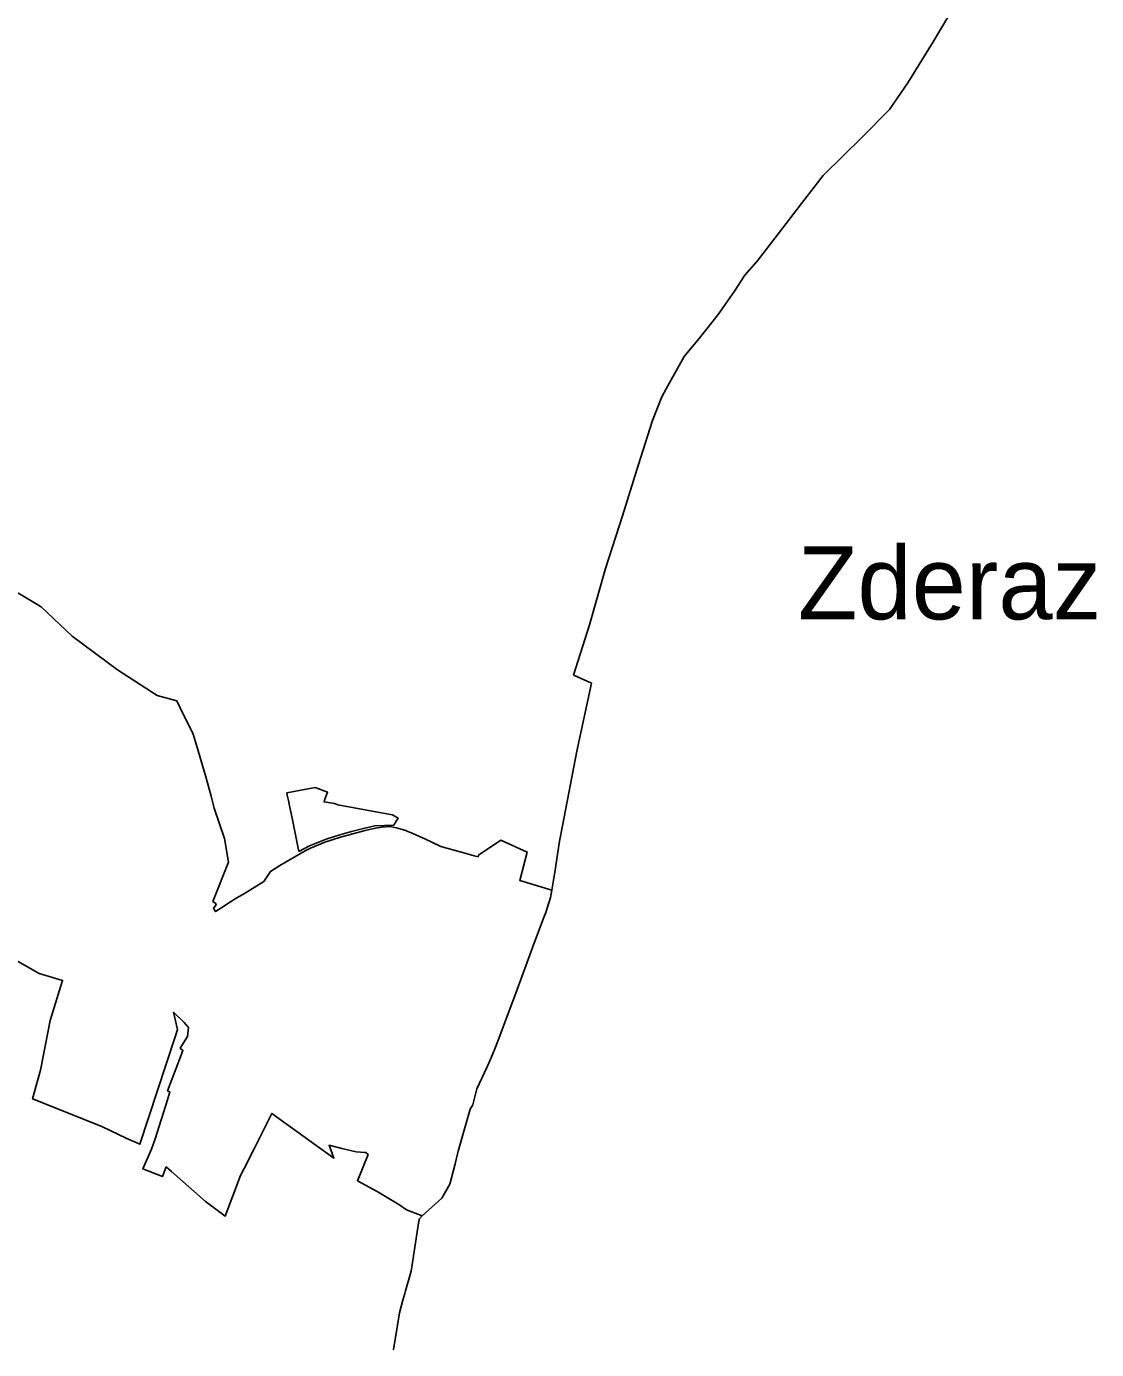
# Model space of a CAD drawing. Extents: x -630160 to -627062, y -1088658 to -1084740.
# Drawn here: x -628278 to -627397, y -1087158 to -1086070 of the extents above; entities that cross this region are included whole.
import ezdxf

# ---------------------------------------------------------------- set-up
doc = ezdxf.new("R2010")
doc.units = 0
for name, color, linetype in [('HRA_KU', 7, 'Continuous'), ('KU_OST', 7, 'Continuous'), ('OVNE_PRE', 7, 'Continuous'), ('OVNE_SET', 7, 'Continuous'), ('OVNI_SET', 7, 'Continuous')]:
    doc.layers.add(name, color=color, linetype=linetype)

msp = doc.modelspace()

# ---------------------------------------------------------------- linework, layer by layer
at = {"layer": 'HRA_KU'}
msp.add_lwpolyline([(-627518.5, -1086060.5), (-627531.4, -1086082.2), (-627552.3, -1086116), (-627567.3, -1086138), (-627589.2, -1086160.1), (-627621.8, -1086192.2), (-627639.7, -1086215.4), (-627658.8, -1086240.1), (-627676.3, -1086262.7), (-627686.3, -1086274.3), (-627695, -1086287.5), (-627708.2, -1086306.6), (-627722.8, -1086325.1), (-627736.2, -1086341.3), (-627751, -1086367.9), (-627754.6, -1086374.4), (-627762.4, -1086394), (-627774.2, -1086430.8), (-627787, -1086472.4), (-627801, -1086515.6), (-627814.2, -1086562.1), (-627827.3, -1086603.4), (-627824.1, -1086604.8), (-627812.7, -1086609.9), (-627824.6, -1086666.1), (-627836.4, -1086727.4), (-627838.8, -1086740.1), (-627842.8, -1086765.5), (-627845.3, -1086780.4), (-627846.4, -1086786.3), (-627850.2, -1086798.7), (-627852, -1086803.5), (-627861.3, -1086828.5), (-627873.8, -1086862.1), (-627890.6, -1086906.9), (-627891, -1086908.3), (-627894.5, -1086917), (-627898.5, -1086925.8), (-627906.9, -1086943.9), (-627910.3, -1086956.9), (-627912.4, -1086960.5), (-627912.4, -1086960.7), (-627922.2, -1086995.2), (-627922.8, -1086997.4), (-627924.9, -1087005.5), (-627929.2, -1087022.2), (-627935.8, -1087033.8), (-627951.8, -1087048.3), (-627954.1, -1087050.7), (-627954.4, -1087051), (-627954.5, -1087051.6), (-627954.9, -1087054.3), (-627961.1, -1087094), (-627965.6, -1087110.2), (-627966.2, -1087112.4), (-627967.7, -1087117.7), (-627970.6, -1087128.1), (-627972.3, -1087138.4), (-627975.1, -1087155), (-627975.6, -1087158), (-627975.7, -1087158.7)], dxfattribs=at)
at = {"layer": 'OVNE_PRE'}
for points in [[(-627518.5, -1086060.5), (-627531.4, -1086082.2), (-627552.3, -1086116), (-627567.3, -1086138), (-627589.2, -1086160.1), (-627621.8, -1086192.2), (-627639.7, -1086215.4), (-627658.8, -1086240.1), (-627676.3, -1086262.7), (-627686.3, -1086274.3), (-627695, -1086287.5), (-627708.2, -1086306.6), (-627722.8, -1086325.1), (-627736.2, -1086341.3), (-627751, -1086367.9), (-627754.6, -1086374.4), (-627762.4, -1086394), (-627774.2, -1086430.8), (-627787, -1086472.4), (-627801, -1086515.6), (-627814.2, -1086562.1), (-627827.3, -1086603.4), (-627824.1, -1086604.8), (-627812.7, -1086609.9), (-627824.6, -1086666.1), (-627836.4, -1086727.4), (-627838.8, -1086740.1), (-627842.8, -1086765.5), (-627845.3, -1086780.4)], [(-627951.8, -1087048.3), (-627954.1, -1087050.7), (-627954.4, -1087051), (-627954.5, -1087051.6), (-627954.9, -1087054.3), (-627961.1, -1087094), (-627965.6, -1087110.2), (-627966.2, -1087112.4), (-627967.7, -1087117.7), (-627970.6, -1087128.1), (-627972.3, -1087138.4), (-627975.6, -1087158), (-627975.7, -1087158.7)]]:
    msp.add_lwpolyline(points, dxfattribs=at)
at = {"layer": 'OVNE_SET'}
for points in [[(-628153.9, -1086624.7), (-628170, -1086620.1), (-628202.7, -1086599.1), (-628240, -1086571.4), (-628265.6, -1086547.2), (-628302, -1086525.6), (-628320.8, -1086509.7), (-628330.2, -1086505.2), (-628353.4, -1086494.1), (-628391.7, -1086475.9), (-628451.3, -1086446), (-628479.9, -1086426.2), (-628501.7, -1086408), (-628505.7, -1086401.9), (-628516.6, -1086382.6), (-628546.4, -1086362)], [(-627964.6, -1086731.6), (-627967.4, -1086730.6), (-627973.1, -1086729), (-627978.4, -1086728.1), (-627985.1, -1086728.5), (-627990.4, -1086729.4), (-627991.8, -1086729.7), (-627998.7, -1086731.3), (-628019.1, -1086736.8), (-628032, -1086740.8), (-628043.7, -1086745.7), (-628048.3, -1086748), (-628053.5, -1086750.9), (-628069.1, -1086760.2), (-628076.8, -1086764.9), (-628082.2, -1086773.3), (-628099.6, -1086783.8), (-628100.7, -1086784.5), (-628105.7, -1086787.6), (-628109.7, -1086790.1), (-628116.8, -1086794.7), (-628121.9, -1086798), (-628123.7, -1086795.2), (-628122.1, -1086793.3), (-628121.5, -1086791.7), (-628124.2, -1086789.6), (-628111.4, -1086757.2), (-628114.7, -1086737.8), (-628123, -1086713), (-628125.7, -1086703), (-628130, -1086687.1), (-628137.7, -1086661), (-628139.5, -1086654.8), (-628140.6, -1086651.3), (-628149, -1086635), (-628153.9, -1086624.7)], [(-627845.3, -1086780.4), (-627857, -1086776.8), (-627871.6, -1086772.3), (-627865.5, -1086749), (-627887.3, -1086739.1), (-627905.5, -1086751.6), (-627905.9, -1086752.9), (-627909.2, -1086752), (-627918.8, -1086749.3), (-627936.5, -1086744.3), (-627949.8, -1086738.2), (-627961.6, -1086732.8), (-627964.5, -1086731.7), (-627964.6, -1086731.6)], [(-628321.8, -1086817.9), (-628267.1, -1086848.9), (-628247.9, -1086854.6), (-628249.3, -1086859), (-628258, -1086887.5), (-628266, -1086928.6), (-628272.5, -1086952.1), (-628215.5, -1086974.9), (-628195.1, -1086984.6), (-628184.3, -1086989.5), (-628155.1, -1086901.1), (-628153.2, -1086895), (-628156.5, -1086880.8), (-628147.9, -1086889.2), (-628144.3, -1086893.3), (-628145.1, -1086900.8), (-628151, -1086910.4), (-628148.8, -1086912.2), (-628149.5, -1086913.7), (-628150.9, -1086917.6), (-628161.4, -1086945.5), (-628159.6, -1086946.4), (-628161.5, -1086952.8), (-628171.7, -1086985.1), (-628174.6, -1086993.6), (-628181.9, -1087009.7), (-628165.5, -1087016), (-628162.6, -1087008.1), (-628158.2, -1087012)], [(-628158.2, -1087012), (-628130.2, -1087036.6), (-628127.3, -1087038.8), (-628114, -1087048.6), (-628101.3, -1087015.1), (-628098.5, -1087009.5), (-628090, -1086992.8), (-628075.6, -1086964.1), (-628024.5, -1087000.8), (-628028.5, -1086990.3), (-628018, -1086992.9), (-628006.2, -1086995.7), (-627999.1, -1086996.2), (-627998.3, -1086996.3), (-627996.5, -1086997.9), (-628005.2, -1087019.5), (-627988.9, -1087028.4), (-627971.1, -1087039), (-627964.7, -1087043.3), (-627951.8, -1087048.3)]]:
    msp.add_lwpolyline(points, dxfattribs=at)
at = {"layer": 'OVNI_SET'}
msp.add_lwpolyline([(-628053.3, -1086748.6), (-628059.2, -1086719.8), (-628060.8, -1086712.3), (-628061.9, -1086706.6), (-628062.9, -1086702.1), (-628063.3, -1086700.2), (-628040.1, -1086696), (-628029.7, -1086699.8), (-628032.2, -1086706.3), (-628032.7, -1086707.8), (-628024.2, -1086709), (-628021.2, -1086710.2), (-627984.1, -1086717), (-627976.4, -1086718.4), (-627971.8, -1086721.1), (-627973.3, -1086723.7), (-627975.3, -1086727), (-627990.9, -1086727.4), (-627999.1, -1086729.3), (-628010, -1086732.1), (-628019.7, -1086734.8), (-628030.1, -1086738), (-628030.9, -1086738.3), (-628044.7, -1086744), (-628053.3, -1086748.6)], dxfattribs=at)

# ---------------------------------------------------------------- texts
at = {"layer": 'KU_OST'}
msp.add_text('Zderaz', height=60, dxfattribs=at).set_placement((-627642.7, -1086557.5))

doc.saveas('drawing.dxf')
